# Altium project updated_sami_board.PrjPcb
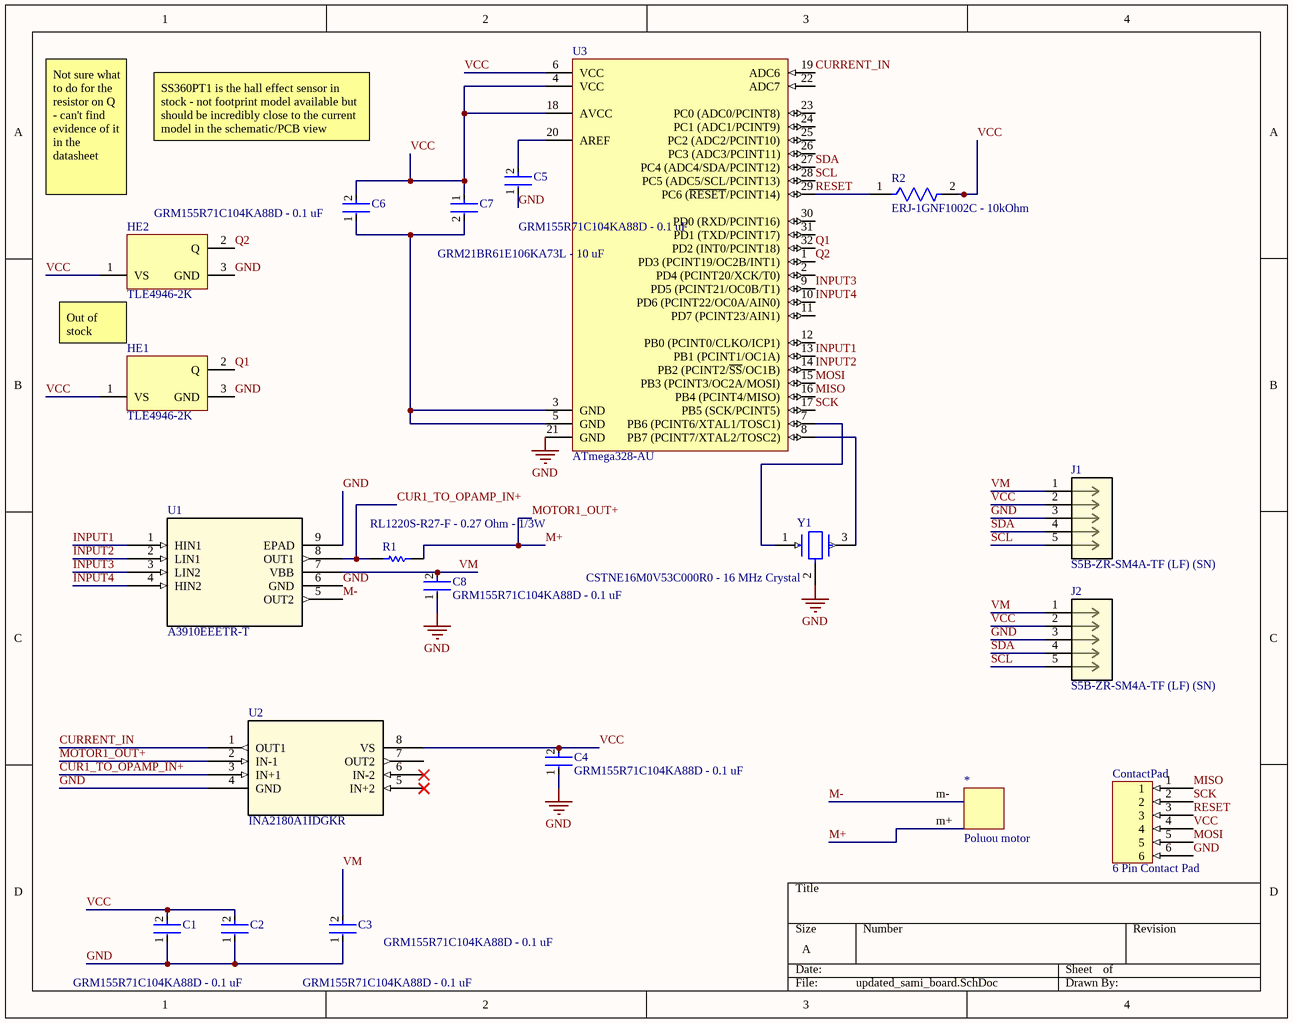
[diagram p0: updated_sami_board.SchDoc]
1 sheet, 20 parts. Net scope: global (net labels, ports and power ports of the same name join across sheets).
Board file: sami_updated.PcbDoc

## Sheet updated_sami_board.SchDoc
size A; SheetNumber: 1; SheetTotal: 1

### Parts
*  Poluou motor  [PCBComponent_1]
C1  GRM155R71C104KA88D - 0.1 uF  [FP-GRM15-MFG]
C2  GRM155R71C104KA88D - 0.1 uF  [FP-GRM15-MFG]
C3  GRM155R71C104KA88D - 0.1 uF  [FP-GRM15-MFG]
C4  GRM155R71C104KA88D - 0.1 uF  [FP-GRM15-MFG]
C5  GRM155R71C104KA88D - 0.1 uF  [FP-GRM15-MFG]
C6  GRM155R71C104KA88D - 0.1 uF  [FP-GRM15-MFG]
C7  GRM21BR61E106KA73L - 10 uF  [FP-GRM21B-0_15-IPC_C]
C8  GRM155R71C104KA88D - 0.1 uF  [FP-GRM15-MFG]
ContactPad  6 Pin Contact Pad  [6PinContactPad]
HE1  TLE4946-2K  [INF-PG-SC59_M]
HE2  TLE4946-2K  [INF-PG-SC59_M]
J1  S5B-ZR-SM4A-TF (LF) (SN)  [CONN_S5B-ZR-SM4A-TF_JST]
J2  S5B-ZR-SM4A-TF (LF) (SN)  [CONN_S5B-ZR-SM4A-TF_JST]
R1  RL1220S-R27-F - 0.27 Ohm - 1/3W  [RESC2013X50X40NL20T20]
R2  ERJ-1GNF1002C - 10kOhm  [FP-ERJ1G-MFG]
U1  A3910EEETR-T  [DFN-8_ALM]
U2  INA2180A1IDGKR  [DGK8_TEX]
U3  ATmega328-AU  [32A_L]
Y1  CSTNE16M0V53C000R0 - 16 MHz Crystal  [FP-CSTNE16M0V53C000R0-MFG]

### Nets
GND: C1.1 C2.1 C3.1 C4.1 C5.1 C8.1 ContactPad.6 HE1.3(GND) HE2.3(GND) J1.3 J2.3 U1.6(GND) U1.9(EPAD) U2.4(GND) U3.21(GND) Y1.2(GND)
CUR1_TO_OPAMP_IN+: R1.1 U1.8(OUT1) U2.3(IN+1)
CURRENT_IN: U2.1(OUT1) U3.19(ADC6)
INPUT1: U1.1(HIN1) U3.13(PB1_(PCINT1/OC1A))
INPUT2: U1.2(LIN1) U3.14(PB2_(PCINT2/~{SS}/OC1B))
INPUT3: U1.3(LIN2) U3.9(PD5_(PCINT21/OC0B/T1))
INPUT4: U1.4(HIN2) U3.10(PD6_(PCINT22/OC0A/AIN0))
M+: *.m+ R1.2 U2.2(IN-1)  [also labelled MOTOR1_OUT+]
M-: *.m- U1.5(OUT2)
MISO: ContactPad.1 U3.16(PB4_(PCINT4/MISO))
MOSI: ContactPad.5 U3.15(PB3_(PCINT3/OC2A/MOSI))
Q1: HE1.2(Q) U3.32(PD2_(INT0/PCINT18))
Q2: HE2.2(Q) U3.1(PD3_(PCINT19/OC2B/INT1))
RESET: ContactPad.3 R2.1 U3.29(PC6_(~{RESET}/PCINT14))
SCK: ContactPad.2 U3.17(PB5_(SCK/PCINT5))
SCL: J1.5 J2.5 U3.28(PC5_(ADC5/SCL/PCINT13))
SDA: J1.4 J2.4 U3.27(PC4_(ADC4/SDA/PCINT12))
VCC: C1.2 C2.2 C4.2 C6.2 C7.1 ContactPad.4 HE1.1(VS) HE2.1(VS) J1.2 J2.2 R2.2 U2.8(VS) U3.4(VCC) U3.6(VCC) U3.18(AVCC)
VM: C3.2 C8.2 J1.1 J2.1 U1.7(VBB)
NetC5_2: C5.2 U3.20(AREF)
NetC6_1: C6.1 C7.2 U3.3(GND) U3.5(GND)
NetU3_7: U3.7(PB6_(PCINT6/XTAL1/TOSC1)) Y1.1(Input)
NetU3_8: U3.8(PB7_(PCINT7/XTAL2/TOSC2)) Y1.3(Output)

Not connected (* = marked no-connect by the designer): U2 5(IN+2)* 6(IN-2)* 7(OUT2); U3 2(PD4_(PCINT20/XCK/T0)) 11(PD7_(PCINT23/AIN1)) 12(PB0_(PCINT0/CLKO/ICP1)) 22(ADC7) 23(PC0_(ADC0/PCINT8)) 24(PC1_(ADC1/PCINT9)) 25(PC2_(ADC2/PCINT10)) 26(PC3_(ADC3/PCINT11)) 30(PD0_(RXD/PCINT16)) 31(PD1_(TXD/PCINT17))

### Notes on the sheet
- SS360PT1 is the hall effect sensor in stock - not footprint model available but should be incredibly close to the current model in the schematic/PCB view
- Not sure what to do for the resistor on Q - can't find evidence of it in the datasheet
- Out of stock

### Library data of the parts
C1-C6 C8 = CMP-2100-03641-2: CAP CER 0.1UF 16V X7R 0402; Manufacturer: Murata; Standoff Height: 0mm; Tolerance: 10%; Voltage Rating: 16Vdc; Material: Ceramic; Capacitance: 0.10μF; Value: 0.10μF
C7 = CMP-2007-03541-2: Chip Multilayer Ceramic Capacitors for General Purpose, 0805, 10uF, X5R, 15%, 10%, 25V
HE1 HE2 = CMP-1148-00006-1: High Precision Hall Effect Latch, PG-SC59, Reel, Green; Manufacturer: Infineon; Brp (25degreesC) typ: -2Â mT; Target Application: Automotive; Interface: open collector; Chopped Hall Technology: TRUE; Bhyst (25degreesC) max: 4Â mT; Direction Detection: FALSE; Bop (25degreesC) min: 2Â mT
J1 J2 = S5B-ZR-SM4A-TF (LF) (SN): No Description Available; Mfr_Name: JST
R1 = CMP-2001-03162-1: Manufacturer: Susumu
R2 = CMP-2004-03445-2: RES SMD 10K OHM 1% 1/20W 0201; Manufacturer: Panasonic Electronic Components; Power Rating: 0.05W; Voltage Rating: 25V; Resistance: 10kΩ; Automotive Grade: Grade 1; Value: 10kΩ; Temperature Coefficient: 200ppm/°C
U1 = A3910EEETR-T: No Description Available; Mfr_Name: Allegro Microsystems Inc.
U2 = INA2180A1IDGKR: No Description Available; Mfr_Name: Texas Instruments
U3 = CMP-0095-00261-2: 8-bit AVR Microcontroller, 32KB Flash, 1KB EEPROM, 2KB SRAM, 32-pin TQFP, Industrial Grade (-40°C to 85°C)
Y1 = CMP-06057-000009-1: CERAMIC RES 16.0000MHZ 15PF SMD; Impedance: 40R; Frequency Stability: 0.15%; Frequency: 16MHz; Frequency Tolerance: 0.5%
